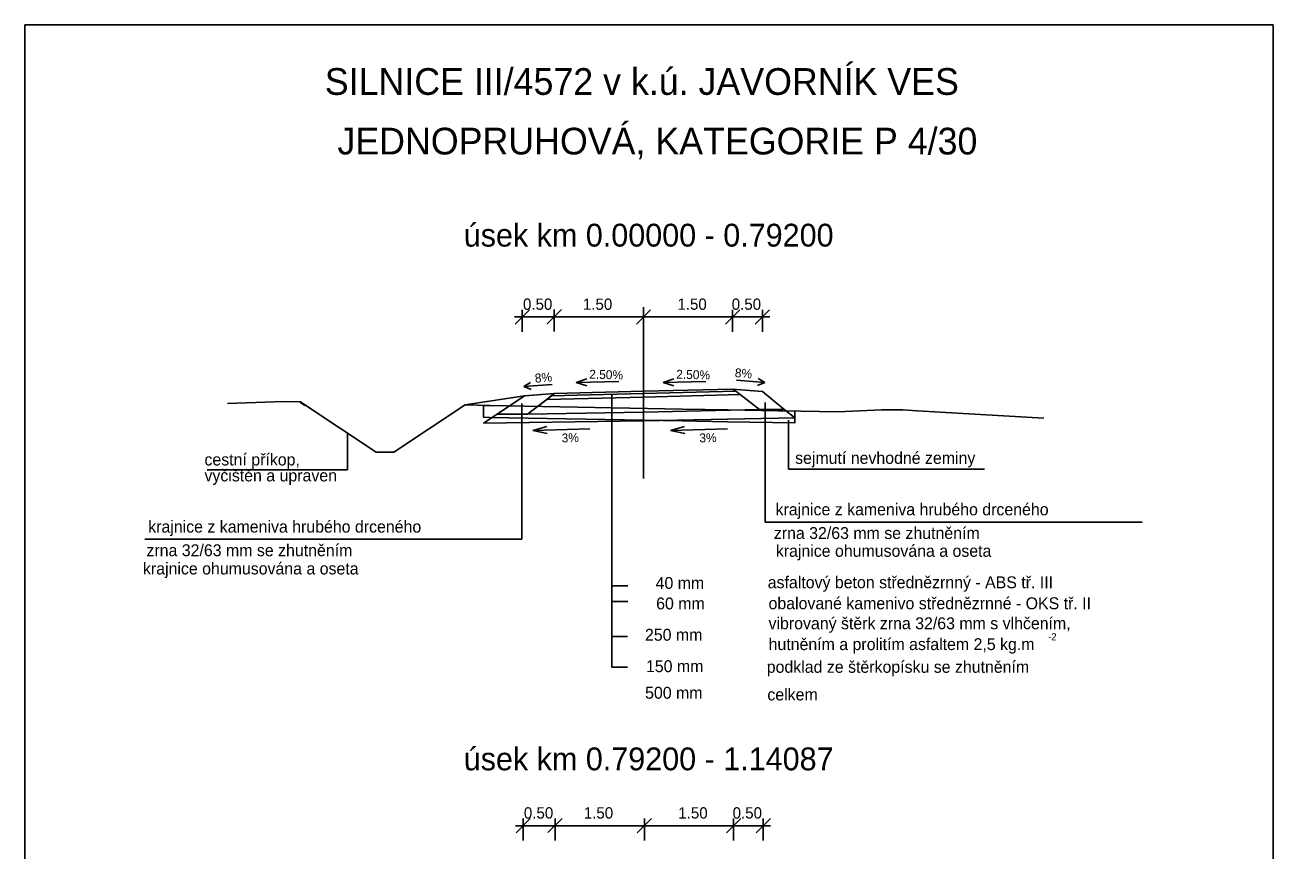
# Model space of a CAD drawing. Extents: x -553158.6 to -553137.6, y -1027695 to -1027665.3.
# Drawn here: x -553158.61 to -553137.61, y -1027679.22 to -1027665.34 of the extents above; entities that cross this region are included whole.
import ezdxf

# ---------------------------------------------------------------- set-up
doc = ezdxf.new("R2010")
doc.units = 0
for name, color, linetype in [('16', 7, 'Continuous'), ('60', 7, 'Continuous'), ('Implicitní', 7, 'Continuous'), ('POPIS', 7, 'Continuous'), ('TERÉN', 7, 'Continuous'), ('WORKING_LAYER', 7, 'Continuous')]:
    doc.layers.add(name, color=color, linetype=linetype)

# ---------------------------------------------------------------- blocks, each defined once
blk = doc.blocks.new('A$C038E1F8A')
at = {"layer": 'Implicitní'}
for p, q in [((0, 0.297), (-0.21, 0.297)), ((-0.21, 0.297), (-0.21, 0)), ((0, 0.297), (0, 0))]:
    blk.add_line(p, q, dxfattribs=at)

msp = doc.modelspace()

# ---------------------------------------------------------------- linework, layer by layer
for p, q in [((-553149.703, -1027671.54), (-553150.203, -1027671.58)), ((-553150.154, -1027671.89), (-553149.703, -1027671.54)), ((-553155.203, -1027671.707), (-553154.251, -1027671.678)), ((-553154.251, -1027671.678), (-553153.974, -1027671.683)), ((-553153.974, -1027671.683), (-553153.903, -1027671.73)), ((-553153.903, -1027671.73), (-553152.703, -1027672.53)), ((-553152.403, -1027672.53), (-553151.203, -1027671.73)), ((-553150.203, -1027671.58), (-553151.203, -1027671.73)), ((-553151.203, -1027671.73), (-553150.788, -1027671.742)), ((-553150.788, -1027671.742), (-553147.546, -1027671.802)), ((-553150.203, -1027671.58), (-553150.668, -1027671.89)), ((-553146.158, -1027673.704), (-553146.158, -1027671.694)), ((-553150.668, -1027671.89), (-553150.154, -1027671.89)), ((-553147.546, -1027671.802), (-553146.785, -1027671.816)), ((-553146.785, -1027671.816), (-553144.933, -1027671.851)), ((-553144.933, -1027671.851), (-553144.191, -1027671.815)), ((-553144.191, -1027671.815), (-553143.841, -1027671.815)), ((-553143.841, -1027671.815), (-553143.6, -1027671.83)), ((-553143.6, -1027671.83), (-553141.465, -1027671.956)), ((-553152.703, -1027672.53), (-553152.403, -1027672.53))]:
    msp.add_line(p, q)
for points in [[(-553148.204, -1027671.543), (-553149.754, -1027671.58), (-553149.832, -1027671.64), (-553148.204, -1027671.603), (-553146.575, -1027671.559), (-553146.652, -1027671.499), (-553148.204, -1027671.543), (-553146.652, -1027671.499), (-553146.703, -1027671.465), (-553148.203, -1027671.503), (-553149.703, -1027671.54), (-553149.754, -1027671.58)], [(-553149.832, -1027671.64), (-553149.754, -1027671.58), (-553148.204, -1027671.543), (-553146.652, -1027671.499), (-553146.575, -1027671.559), (-553148.204, -1027671.603)], [(-553146.703, -1027671.465), (-553146.203, -1027671.505), (-553145.842, -1027671.803), (-553146.253, -1027671.809), (-553146.575, -1027671.559), (-553146.652, -1027671.499)], [(-553153.903, -1027671.73), (-553153.974, -1027671.683), (-553153.974, -1027671.693), (-553153.903, -1027671.74)], [(-553150.893, -1027671.74), (-553150.788, -1027671.742), (-553147.546, -1027671.802), (-553146.785, -1027671.816), (-553145.657, -1027671.837), (-553145.657, -1027672.037), (-553146.789, -1027672.016), (-553147.55, -1027672.002), (-553150.792, -1027671.942), (-553150.893, -1027671.94)], [(-553150.154, -1027671.89), (-553149.832, -1027671.64), (-553148.204, -1027671.603), (-553146.575, -1027671.559), (-553146.253, -1027671.809), (-553148.204, -1027671.853)], [(-553150.893, -1027672.04), (-553150.668, -1027671.89), (-553150.154, -1027671.89), (-553148.204, -1027671.853), (-553146.253, -1027671.809), (-553145.842, -1027671.803), (-553145.657, -1027671.953), (-553148.204, -1027672.003)]]:
    msp.add_lwpolyline(points, close=True)
msp.add_lwpolyline([(-553153.903, -1027671.73), (-553153.974, -1027671.683)])
at = {"layer": '60'}
msp.add_line((-553148.203, -1027670.09), (-553148.203, -1027672.97), dxfattribs=at)
at = {"layer": 'POPIS'}
for p, q in [((-553150.249, -1027671.709), (-553150.249, -1027673.993)), ((-553148.735, -1027676.146), (-553148.735, -1027671.557)), ((-553145.763, -1027671.988), (-553145.763, -1027672.814)), ((-553153.181, -1027672.212), (-553153.181, -1027672.828)), ((-553155.544, -1027672.828), (-553153.181, -1027672.828)), ((-553145.763, -1027672.814), (-553142.468, -1027672.814)), ((-553146.158, -1027673.704), (-553139.811, -1027673.704)), ((-553150.249, -1027673.993), (-553156.595, -1027673.993)), ((-553148.735, -1027674.779), (-553148.466, -1027674.779)), ((-553148.735, -1027675.043), (-553148.466, -1027675.043)), ((-553148.475, -1027675.629), (-553148.735, -1027675.629)), ((-553148.475, -1027676.146), (-553148.735, -1027676.146))]:
    msp.add_line(p, q, dxfattribs=at)
at = {"layer": 'WORKING_LAYER'}
for p, q in [((-553150.374, -1027670.252), (-553146.079, -1027670.252)), ((-553150.363, -1027670.372), (-553150.123, -1027670.132)), ((-553150.363, -1027670.372), (-553150.123, -1027670.132)), ((-553150.243, -1027670.502), (-553150.243, -1027670.132)), ((-553149.825, -1027670.369), (-553149.585, -1027670.129)), ((-553149.705, -1027670.499), (-553149.705, -1027670.129)), ((-553148.323, -1027670.372), (-553148.083, -1027670.132)), ((-553148.203, -1027670.502), (-553148.203, -1027670.132)), ((-553148.203, -1027670.502), (-553148.203, -1027670.132)), ((-553146.823, -1027670.372), (-553146.583, -1027670.132)), ((-553146.823, -1027670.372), (-553146.583, -1027670.132)), ((-553146.703, -1027670.502), (-553146.703, -1027670.132)), ((-553146.323, -1027670.372), (-553146.083, -1027670.132)), ((-553146.203, -1027670.502), (-553146.203, -1027670.132)), ((-553146.203, -1027670.502), (-553146.203, -1027670.132)), ((-553149.159, -1027671.292), (-553149.337, -1027671.357)), ((-553149.337, -1027671.357), (-553148.617, -1027671.339)), ((-553147.695, -1027671.292), (-553147.873, -1027671.357)), ((-553147.873, -1027671.357), (-553147.154, -1027671.339)), ((-553146.637, -1027671.317), (-553146.159, -1027671.356)), ((-553146.637, -1027671.317), (-553146.159, -1027671.356)), ((-553146.274, -1027671.286), (-553146.159, -1027671.356)), ((-553150.103, -1027671.356), (-553150.218, -1027671.425)), ((-553150.218, -1027671.425), (-553149.739, -1027671.387)), ((-553150.218, -1027671.425), (-553150.093, -1027671.475)), ((-553149.337, -1027671.357), (-553149.156, -1027671.412)), ((-553148.203, -1027671.53), (-553148.203, -1027671.53)), ((-553147.873, -1027671.357), (-553147.692, -1027671.412)), ((-553146.159, -1027671.356), (-553146.283, -1027671.406)), ((-553146.159, -1027671.356), (-553146.283, -1027671.406)), ((-553150.067, -1027672.162), (-553149.829, -1027672.095)), ((-553150.067, -1027672.162), (-553149.107, -1027672.133)), ((-553149.825, -1027672.215), (-553150.067, -1027672.162)), ((-553147.75, -1027672.162), (-553147.511, -1027672.095)), ((-553147.75, -1027672.162), (-553146.79, -1027672.133)), ((-553147.508, -1027672.215), (-553147.75, -1027672.162)), ((-553149.81, -1027678.931), (-553149.57, -1027678.691)), ((-553149.69, -1027679.061), (-553149.69, -1027678.691)), ((-553150.359, -1027678.814), (-553146.064, -1027678.814)), ((-553150.348, -1027678.934), (-553150.108, -1027678.694)), ((-553150.348, -1027678.934), (-553150.108, -1027678.694)), ((-553150.228, -1027679.064), (-553150.228, -1027678.694)), ((-553148.308, -1027678.934), (-553148.068, -1027678.694)), ((-553148.188, -1027679.064), (-553148.188, -1027678.694)), ((-553148.188, -1027679.064), (-553148.188, -1027678.694)), ((-553146.808, -1027678.934), (-553146.568, -1027678.694)), ((-553146.808, -1027678.934), (-553146.568, -1027678.694)), ((-553146.688, -1027679.064), (-553146.688, -1027678.694)), ((-553146.308, -1027678.934), (-553146.068, -1027678.694)), ((-553146.188, -1027679.064), (-553146.188, -1027678.694)), ((-553146.188, -1027679.064), (-553146.188, -1027678.694))]:
    msp.add_line(p, q, dxfattribs=at)

# ---------------------------------------------------------------- block references
at = {"layer": 'Implicitní', "xscale": 100, "yscale": 100}
msp.add_blockref('A$C038E1F8A', (-553137.611, -1027695.038), dxfattribs=at)

# ---------------------------------------------------------------- texts
at = {"layer": '16'}
for p in [(-553149.118, -1027671.291), (-553147.654, -1027671.291)]:
    msp.add_text('2.50%', height=0.15, rotation=358.5679, dxfattribs=at).set_placement(p)
at = {"layer": 'POPIS'}
for s, height, p in [('SILNICE III/4572 v k.ú. JAVORNÍK VES', 0.45, (-553153.565, -1027666.515)), ('JEDNOPRUHOVÁ, KATEGORIE P 4/30', 0.45, (-553153.353, -1027667.518)), ('úsek km 0.00000 - 0.79200', 0.384, (-553151.228, -1027669.068)), ('cestní příkop,', 0.2, (-553155.59, -1027672.752)), ('sejmutí nevhodné zeminy', 0.2, (-553145.652, -1027672.725)), ('vyčištěn a upraven', 0.2, (-553155.59, -1027673.02)), ('krajnice z kameniva hrubého drceného', 0.2, (-553145.981, -1027673.591)), ('krajnice z kameniva hrubého drceného', 0.2, (-553156.537, -1027673.881)), ('zrna 32/63 mm se zhutněním', 0.2, (-553146.01, -1027673.989)), ('zrna 32/63 mm se zhutněním', 0.2, (-553156.566, -1027674.279)), ('krajnice ohumusována a oseta', 0.2, (-553145.977, -1027674.289)), ('krajnice ohumusována a oseta', 0.2, (-553156.625, -1027674.586)), ('podklad ze štěrkopísku se zhutněním', 0.2, (-553146.129, -1027676.241)), ('celkem', 0.2, (-553146.119, -1027676.706)), ('úsek km 0.79200 - 1.14087', 0.384, (-553151.228, -1027677.882))]:
    msp.add_text(s, height=height, dxfattribs=at).set_placement(p)
at = {"layer": 'TERÉN'}
for s, height, p in [('40 mm', 0.2, (-553147.999, -1027674.829)), ('asfaltový beton střednězrnný - ABS tř. III', 0.2, (-553146.113, -1027674.818)), ('60 mm', 0.2, (-553147.99, -1027675.174)), ('obalované kamenivo střednězrnné - OKS tř. II', 0.2, (-553146.099, -1027675.171)), ('vibrovaný štěrk zrna 32/63 mm s vlhčením,', 0.2, (-553146.099, -1027675.508)), ('250 mm', 0.2, (-553148.178, -1027675.701)), ('hutněním a prolitím asfaltem 2,5 kg.m', 0.2, (-553146.098, -1027675.859)), ('-2', 0.12, (-553141.395, -1027675.695)), ('150 mm  ', 0.2, (-553148.161, -1027676.23)), ('500 mm  ', 0.2, (-553148.176, -1027676.677))]:
    msp.add_text(s, height=height, dxfattribs=at).set_placement(p)
at = {"layer": 'WORKING_LAYER'}
for s, p in [('0.50', (-553150.231, -1027670.132)), ('1.50', (-553149.223, -1027670.132)), ('1.50', (-553147.633, -1027670.132)), ('0.50', (-553146.719, -1027670.132)), ('0.50', (-553150.216, -1027678.694)), ('1.50', (-553149.208, -1027678.694)), ('1.50', (-553147.618, -1027678.694)), ('0.50', (-553146.704, -1027678.694))]:
    msp.add_text(s, height=0.19, dxfattribs=at).set_placement(p)
for s, rotation, p in [('8%', 355.4251, (-553146.671, -1027671.264)), ('8%', 4.5749, (-553150.026, -1027671.359)), ('3%', 1.7185, (-553149.578, -1027672.365)), ('3%', 1.7185, (-553147.261, -1027672.365))]:
    msp.add_text(s, height=0.15, rotation=rotation, dxfattribs=at).set_placement(p)

doc.saveas('drawing.dxf')
